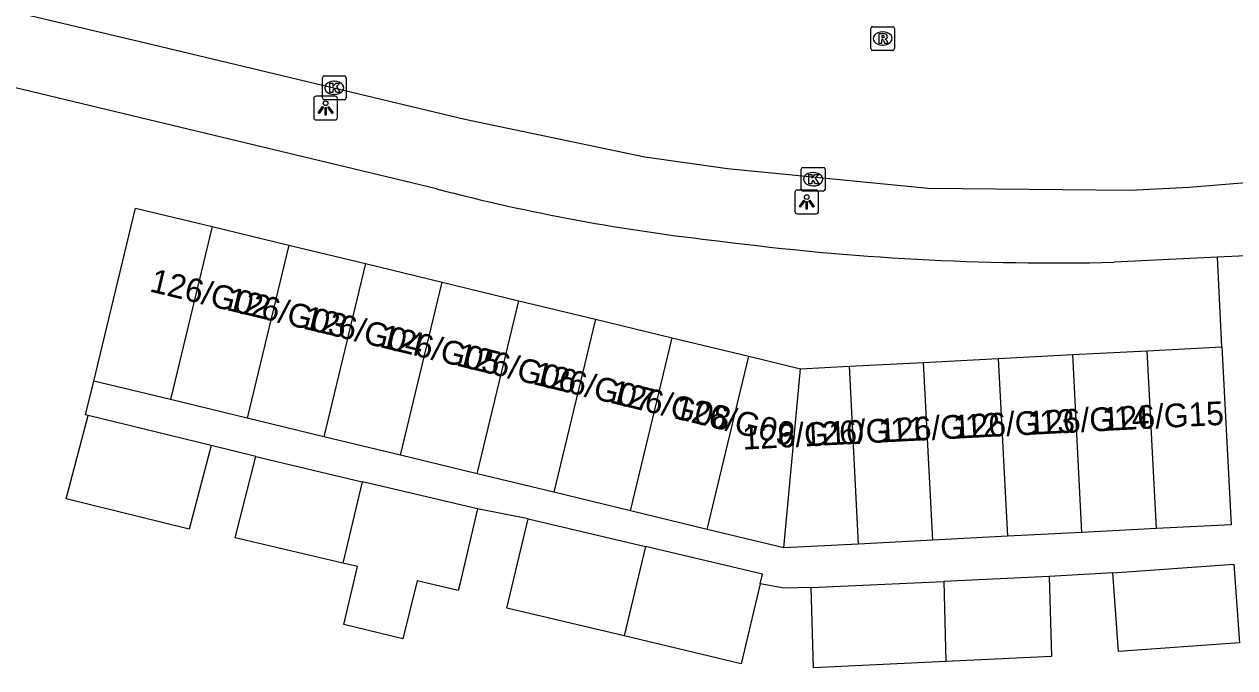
# Model space of a CAD drawing. Extents: x 161084 to 161928, y 385355 to 386522.
# Drawn here: x 161534.8 to 161585.8, y 385783.4 to 385810.5 of the extents above; entities that cross this region are included whole.
import ezdxf

# ---------------------------------------------------------------- set-up
doc = ezdxf.new("R2010")
doc.units = 0
for name, color, linetype in [('IMGEO_Kolk', 7, 'Continuous'), ('IMGEO_Lichtpunt', 7, 'Continuous'), ('IMGEO_Pand', 7, 'Continuous'), ('IMGEO_Pand_nummerreeks', 7, 'Continuous'), ('IMGEO_Rijbaan_lokaal_open', 7, 'Continuous'), ('IMGEO_Rioolput', 7, 'Continuous'), ('IMGEO_Voetpad_open', 7, 'Continuous')]:
    doc.layers.add(name, color=color, linetype=linetype)

msp = doc.modelspace()

# ---------------------------------------------------------------- linework, layer by layer
at = {"layer": 'IMGEO_Kolk'}
for p, q in [((161547.332, 385807.434), (161547.332, 385808.286)), ((161547.407, 385808.36), (161548.259, 385808.36)), ((161547.82, 385808.14), (161547.845, 385808.14)), ((161548.333, 385808.286), (161548.333, 385807.434)), ((161547.843, 385807.58), (161547.818, 385807.58)), ((161548.259, 385807.36), (161547.407, 385807.36)), ((161567.572, 385804.509), (161568.424, 385804.509)), ((161567.497, 385803.583), (161567.497, 385804.435)), ((161567.985, 385804.289), (161568.01, 385804.289)), ((161568.498, 385804.435), (161568.498, 385803.583)), ((161568.424, 385803.509), (161567.572, 385803.509)), ((161568.008, 385803.729), (161567.983, 385803.729))]:
    msp.add_line(p, q, dxfattribs=at)
for points in [[(161547.332, 385807.434), (161547.332, 385808.286)], [(161547.407, 385808.36), (161548.259, 385808.36)], [(161547.653, 385808.06), (161547.776, 385808.06), (161547.776, 385807.909), (161547.906, 385808.06), (161548.07, 385808.06), (161547.924, 385807.909), (161548.077, 385807.66), (161547.925, 385807.66), (161547.84, 385807.824), (161547.776, 385807.757), (161547.776, 385807.66), (161547.653, 385807.66), (161547.653, 385808.06)], [(161548.333, 385808.286), (161548.333, 385807.434)], [(161548.259, 385807.36), (161547.407, 385807.36)], [(161567.572, 385804.509), (161568.424, 385804.509)], [(161567.497, 385803.583), (161567.497, 385804.435)], [(161567.818, 385804.209), (161567.941, 385804.209), (161567.941, 385804.058), (161568.071, 385804.209), (161568.235, 385804.209), (161568.089, 385804.058), (161568.242, 385803.809), (161568.09, 385803.809), (161568.005, 385803.973), (161567.941, 385803.906), (161567.941, 385803.809), (161567.818, 385803.809), (161567.818, 385804.209)], [(161568.498, 385804.435), (161568.498, 385803.583)], [(161568.424, 385803.509), (161567.572, 385803.509)]]:
    msp.add_lwpolyline(points, dxfattribs=at)
for centre, start, end in [((161547.409, 385808.284), 91.552, 178.448), ((161547.409, 385808.284), 91.552, 178.448), ((161548.257, 385808.284), 1.552, 88.448), ((161548.257, 385808.284), 1.552, 88.448), ((161547.409, 385807.436), 181.552, 268.448), ((161547.409, 385807.436), 181.552, 268.448), ((161548.257, 385807.436), 271.552, 358.448), ((161548.257, 385807.436), 271.552, 358.448), ((161567.574, 385804.433), 91.552, 178.448), ((161567.574, 385804.433), 91.552, 178.448), ((161568.422, 385804.433), 1.552, 88.448), ((161568.422, 385804.433), 1.552, 88.448), ((161567.574, 385803.585), 181.552, 268.448), ((161567.574, 385803.585), 181.552, 268.448), ((161568.422, 385803.585), 271.552, 358.448), ((161568.422, 385803.585), 271.552, 358.448)]:
    msp.add_arc(centre, 0.0765, start, end, dxfattribs=at)
for centre, major_axis, ratio, start_param, end_param in [((161547.819, 385807.86), (-0.387, 0.002), 0.722429, 4.712389, 7.853982), ((161547.844, 385807.86), (-0.39, 0.002), 0.717154, 1.570796, 4.712389), ((161567.984, 385804.009), (-0.387, 0.002), 0.722429, 4.712389, 7.853982), ((161568.009, 385804.009), (-0.39, 0.002), 0.717154, 1.570796, 4.712389)]:
    msp.add_ellipse(centre, major_axis=major_axis, ratio=ratio, start_param=start_param, end_param=end_param, dxfattribs=at)
at = {"layer": 'IMGEO_Lichtpunt'}
for p, q in [((161546.971, 385807.411), (161546.971, 385806.604)), ((161546.971, 385807.411), (161546.971, 385806.604)), ((161547.873, 385807.506), (161547.065, 385807.506)), ((161547.873, 385807.506), (161547.065, 385807.506)), ((161547.967, 385806.604), (161547.967, 385807.411)), ((161547.967, 385806.604), (161547.967, 385807.411)), ((161547.065, 385806.51), (161547.873, 385806.51)), ((161547.065, 385806.51), (161547.873, 385806.51)), ((161567.23, 385803.46), (161567.23, 385802.653)), ((161567.23, 385803.46), (161567.23, 385802.653)), ((161568.132, 385803.555), (161567.324, 385803.555)), ((161568.132, 385803.555), (161567.324, 385803.555)), ((161568.226, 385802.653), (161568.226, 385803.46)), ((161568.226, 385802.653), (161568.226, 385803.46)), ((161567.324, 385802.559), (161568.132, 385802.559)), ((161567.324, 385802.559), (161568.132, 385802.559))]:
    msp.add_line(p, q, dxfattribs=at)
for points in [[(161547.345, 385807.075), (161547.384, 385807.047), (161547.196, 385806.785), (161547.158, 385806.812), (161547.345, 385807.075)], [(161547.447, 385807.027), (161547.494, 385807.027), (161547.494, 385806.705), (161547.447, 385806.705), (161547.447, 385807.027)], [(161547.557, 385807.047), (161547.595, 385807.074), (161547.782, 385806.812), (161547.743, 385806.784), (161547.557, 385807.047)], [(161567.604, 385803.124), (161567.643, 385803.096), (161567.455, 385802.834), (161567.417, 385802.861), (161567.604, 385803.124)], [(161567.706, 385803.076), (161567.753, 385803.076), (161567.753, 385802.754), (161567.706, 385802.754), (161567.706, 385803.076)], [(161567.816, 385803.096), (161567.854, 385803.123), (161568.041, 385802.861), (161568.002, 385802.833), (161567.816, 385803.096)]]:
    msp.add_lwpolyline(points, dxfattribs=at)
for centre in [(161547.47, 385807.209), (161567.729, 385803.258)]:
    msp.add_circle(centre, 0.0994, dxfattribs=at)
for centre, start, end in [((161547.065, 385807.411), 90, 180), ((161547.065, 385807.411), 90, 180), ((161547.873, 385807.411), 0, 90), ((161547.873, 385807.411), 0, 90), ((161547.065, 385806.604), 180, 270), ((161547.065, 385806.604), 180, 270), ((161547.873, 385806.604), 270, 0), ((161547.873, 385806.604), 270, 360), ((161567.324, 385803.46), 90, 180), ((161567.324, 385803.46), 90, 180), ((161568.132, 385803.46), 0, 90), ((161568.132, 385803.46), 0, 90), ((161567.324, 385802.653), 180, 270), ((161567.324, 385802.653), 180, 270), ((161568.132, 385802.653), 270, 0), ((161568.132, 385802.653), 270, 360)]:
    msp.add_arc(centre, 0.0946, start, end, dxfattribs=at)
at = {"layer": 'IMGEO_Pand'}
for points in [[(161537.706, 385795.508), (161539.469, 385802.798), (161542.697, 385802.017)], [(161542.697, 385802.017), (161540.934, 385794.727)], [(161542.697, 385802.017), (161545.925, 385801.237)], [(161545.925, 385801.237), (161544.162, 385793.947)], [(161545.925, 385801.237), (161549.153, 385800.456)], [(161549.153, 385800.456), (161547.391, 385793.166)], [(161549.153, 385800.456), (161552.382, 385799.676)], [(161550.619, 385792.386), (161552.382, 385799.676)], [(161552.382, 385799.676), (161555.61, 385798.895)], [(161553.847, 385791.605), (161555.61, 385798.895)], [(161555.61, 385798.895), (161558.838, 385798.115)], [(161558.838, 385798.115), (161557.075, 385790.825)], [(161558.838, 385798.115), (161562.066, 385797.334)], [(161560.304, 385790.044), (161562.066, 385797.334)], [(161562.066, 385797.334), (161565.294, 385796.553)], [(161582.069, 385796.785), (161585.207, 385796.947)], [(161585.207, 385796.947), (161585.595, 385789.457), (161582.456, 385789.295)], [(161563.532, 385789.264), (161565.294, 385796.553)], [(161565.294, 385796.553), (161567.463, 385796.029)], [(161572.651, 385796.297), (161575.79, 385796.46)], [(161575.79, 385796.46), (161578.929, 385796.622)], [(161575.79, 385796.46), (161576.178, 385788.97)], [(161578.929, 385796.622), (161582.069, 385796.785)], [(161579.317, 385789.132), (161578.929, 385796.622)], [(161582.456, 385789.295), (161582.069, 385796.785)], [(161566.76, 385788.483), (161567.463, 385796.029)], [(161567.463, 385796.029), (161569.512, 385796.135)], [(161569.512, 385796.135), (161572.651, 385796.297)], [(161569.512, 385796.135), (161569.899, 385788.645)], [(161573.038, 385788.808), (161572.651, 385796.297)], [(161540.934, 385794.727), (161537.706, 385795.508)], [(161544.162, 385793.947), (161540.934, 385794.727)], [(161542.645, 385792.795), (161541.725, 385789.276), (161536.551, 385790.545), (161537.471, 385794.064)], [(161542.645, 385792.795), (161537.471, 385794.064)], [(161547.391, 385793.166), (161544.162, 385793.947)], [(161550.619, 385792.386), (161547.391, 385793.166)], [(161548.194, 385787.84), (161543.664, 385788.912), (161544.535, 385792.332)], [(161544.535, 385792.332), (161549.007, 385791.272)], [(161553.847, 385791.605), (161550.619, 385792.386)], [(161549.007, 385791.272), (161548.194, 385787.84)], [(161553.871, 385790.121), (161549.627, 385791.126), (161549.007, 385791.272)], [(161557.075, 385790.825), (161553.847, 385791.605)], [(161560.304, 385790.044), (161557.075, 385790.825)], [(161553.871, 385790.121), (161553.122, 385786.96), (161553.057, 385786.688), (161551.325, 385787.098), (161550.726, 385784.648), (161548.237, 385785.257), (161548.813, 385787.693), (161548.194, 385787.84)], [(161560.04, 385784.776), (161555.106, 385785.946), (161555.999, 385789.712)], [(161555.999, 385789.712), (161560.933, 385788.542)], [(161563.532, 385789.264), (161560.304, 385790.044)], [(161566.76, 385788.483), (161563.532, 385789.264)], [(161582.456, 385789.295), (161579.317, 385789.132)], [(161573.038, 385788.808), (161569.899, 385788.645)], [(161576.178, 385788.97), (161573.038, 385788.808)], [(161579.317, 385789.132), (161576.178, 385788.97)], [(161560.933, 385788.542), (161560.04, 385784.776)], [(161565.773, 385786.975), (161565.867, 385787.372), (161560.933, 385788.542)], [(161569.899, 385788.645), (161566.76, 385788.483)], [(161580.616, 385787.43), (161585.708, 385787.795), (161585.945, 385784.489)], [(161577.937, 385787.278), (161573.496, 385787.07)], [(161577.937, 385787.278), (161578.031, 385783.903), (161573.59, 385783.695)], [(161585.945, 385784.489), (161580.853, 385784.124), (161580.616, 385787.43)], [(161565.773, 385786.975), (161564.974, 385783.606), (161560.04, 385784.776)], [(161567.911, 385786.808), (161573.496, 385787.07)], [(161573.59, 385783.695), (161568.006, 385783.433), (161567.911, 385786.808)], [(161573.496, 385787.07), (161573.59, 385783.695)]]:
    msp.add_lwpolyline(points, dxfattribs=at)
at = {"layer": 'IMGEO_Rijbaan_lokaal_open'}
msp.add_lwpolyline([(161351.902, 385854.625), (161361.37, 385852.342), (161406.44, 385841.585), (161439.496, 385833.681), (161487.09, 385822.28), (161490.645, 385821.437), (161540.178, 385809.69), (161553.334, 385806.533), (161560.913, 385804.952), (161564.397, 385804.459), (161572.843, 385803.627), (161581.329, 385803.552), (161583.838, 385803.676), (161586.385, 385803.89), (161616.338, 385805.286)], dxfattribs=at)
at = {"layer": 'IMGEO_Rioolput'}
for p, q in [((161570.426, 385809.509), (161570.426, 385810.361)), ((161570.501, 385810.435), (161571.353, 385810.435)), ((161570.914, 385810.215), (161570.939, 385810.215)), ((161571.427, 385810.361), (161571.427, 385809.509)), ((161570.937, 385809.655), (161570.912, 385809.655)), ((161571.353, 385809.435), (161570.501, 385809.435))]:
    msp.add_line(p, q, dxfattribs=at)
for points in [[(161570.426, 385809.509), (161570.426, 385810.361)], [(161570.501, 385810.435), (161571.353, 385810.435)], [(161571.015, 385810.133), (161570.763, 385810.135), (161570.763, 385809.735)], [(161571.427, 385810.361), (161571.427, 385809.509)], [(161570.763, 385809.735), (161570.887, 385809.735), (161570.887, 385809.897), (161570.898, 385809.897)], [(161570.941, 385810.054), (161570.887, 385810.054), (161570.887, 385809.973)], [(161570.887, 385809.973), (161570.939, 385809.973)], [(161570.945, 385809.868), (161571.016, 385809.735), (161571.156, 385809.735), (161571.091, 385809.861)], [(161571.353, 385809.435), (161570.501, 385809.435)]]:
    msp.add_lwpolyline(points, dxfattribs=at)
for centre, radius, start, end in [((161570.503, 385810.359), 0.0765, 91.552, 178.448), ((161570.503, 385810.359), 0.0765, 91.552, 178.448), ((161571.014, 385810.023), 0.109, 350.3612, 89.416), ((161571.351, 385810.359), 0.0765, 1.552, 88.448), ((161571.351, 385810.359), 0.0765, 1.552, 88.448), ((161570.897, 385809.844), 0.0533, 26.0293, 88.6989), ((161570.923, 385810.162), 0.19, 274.7715, 282.9687), ((161570.947, 385809.958), 0.0964, 77.0061, 93.1865), ((161570.961, 385810.015), 0.0378, 276.6634, 79.6772), ((161571.012, 385810.023), 0.112, 277.5842, 350.9817), ((161570.996, 385809.808), 0.108, 29.5134, 73.7905), ((161570.503, 385809.511), 0.0765, 181.552, 268.448), ((161570.503, 385809.511), 0.0765, 181.552, 268.448), ((161571.351, 385809.511), 0.0765, 271.552, 358.448), ((161571.351, 385809.511), 0.0765, 271.552, 358.448)]:
    msp.add_arc(centre, radius, start, end, dxfattribs=at)
for centre, major_axis, ratio, start_param, end_param in [((161570.913, 385809.935), (-0.387, 0.002), 0.722429, 4.712389, 7.853982), ((161570.938, 385809.935), (-0.39, 0.002), 0.717154, 1.570796, 4.712389)]:
    msp.add_ellipse(centre, major_axis=major_axis, ratio=ratio, start_param=start_param, end_param=end_param, dxfattribs=at)
at = {"layer": 'IMGEO_Voetpad_open'}
for points in [[(161552.134, 385803.608), (161500, 385816.134), (161468.662, 385823.663)], [(161585.028, 385800.728), (161580.677, 385800.511)], [(161586.527, 385800.803), (161585.028, 385800.728)], [(161585.207, 385796.947), (161585.028, 385800.728)], [(161537.471, 385794.064), (161537.363, 385794.09), (161537.706, 385795.508)], [(161544.535, 385792.332), (161542.645, 385792.795)], [(161555.999, 385789.712), (161553.871, 385790.121)], [(161580.616, 385787.43), (161577.937, 385787.278)], [(161567.911, 385786.808), (161566.784, 385786.792), (161565.773, 385786.975)]]:
    msp.add_lwpolyline(points, dxfattribs=at)
for centre, radius, start, end in [((161573.073, 385883.686), 82.77, 255.34612, 263.77284), ((161578.207, 385909.054), 108.571, 262.53138, 271.30341)]:
    msp.add_arc(centre, radius, start, end, dxfattribs=at)

# ---------------------------------------------------------------- texts
at = {"layer": 'IMGEO_Pand_nummerreeks'}
for s, rotation, p in [('126/G02', 346.4067, (161540.02, 385799.29)), ('126/G03', 346.4067, (161543.249, 385798.51)), ('126/G04', 346.4067, (161546.477, 385797.729)), ('126/G05', 346.4067, (161549.705, 385796.948)), ('126/G06', 346.4067, (161552.933, 385796.168)), ('126/G07', 346.4067, (161556.161, 385795.387)), ('126/G08', 346.4067, (161559.39, 385794.607)), ('126/G09', 346.4067, (161562.088, 385793.954)), ('126/G13', 2.9616, (161573.913, 385793.078)), ('126/G14', 2.9616, (161577.052, 385793.241)), ('126/G15', 2.9616, (161580.191, 385793.403)), ('126/G10', 2.9616, (161565.041, 385792.619)), ('126/G11', 2.9616, (161567.635, 385792.753)), ('126/G12', 2.9616, (161570.774, 385792.916))]:
    msp.add_text(s, height=1, rotation=rotation, dxfattribs=at).set_placement(p)

doc.saveas('drawing.dxf')
